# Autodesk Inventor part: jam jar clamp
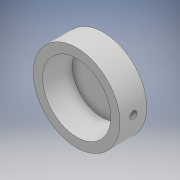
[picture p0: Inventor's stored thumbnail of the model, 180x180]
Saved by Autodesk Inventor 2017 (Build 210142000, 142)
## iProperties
Created: 2016-12
Part Number: jam jar clamp
Material: Generic
Document SubType Name: Modeling
Designer: malcolm
Mass: 203.155 g
Surface Area: 450.455 cm^2
Volume: 203.155 cm^3
Density: 1 g/cm^3
Appearance: Default
Author: malcolm
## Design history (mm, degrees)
sketch "Sketch1"
  geometry: C1 r 60 at (0, 0); 1 further point
  constraints: 1 centre point, 1 coincident
  dimensions: "d0" = 120 diameter of C1
extrude "Extrusion1" new body sketch "Sketch1" distance "d1" = 35; taper "d2" = 0 deg
hole "Hole1" diameter "d5" = 82; stored, may be unused: countersink angle "d9" = 90 deg, drill point angle "d11" = 118 deg; dims "d6" = 6, "d7" = 4, "d8" = 2, "d10" = 8, "d15" = 10, "d16" = 10
feature "FaceDraft1" dims angle "d12" = 10 deg
sketch "Sketch2"
  geometry: C1 r 60 at (0, 0); C2 r 60 at (0, 0) reference; 1 further point
  constraints: 1 centre point, 1 coincident, 1 concentric
extrude "Extrusion2" join sketch "Sketch2" distance "d13" = 2; taper "d14" = 0 deg
sketch "Sketch3"
  geometry: L1 (0, 60)-(0, -60) reference; L2 (0, 60)-(37, 60) reference; C1 r 5 at (18.5, 0); 1 further point
  constraints: 1 centre point
  dimensions: "d17" = 10 diameter of C1; "d18" = 18.5 distance from line of L1 C1.centre; "d19" = 60 distance from line of L2 C1.centre
extrude "Extrusion3" cut sketch "Sketch3" stored distance "d20" = 10; taper "d21" = 0 deg
body "Solid1"
